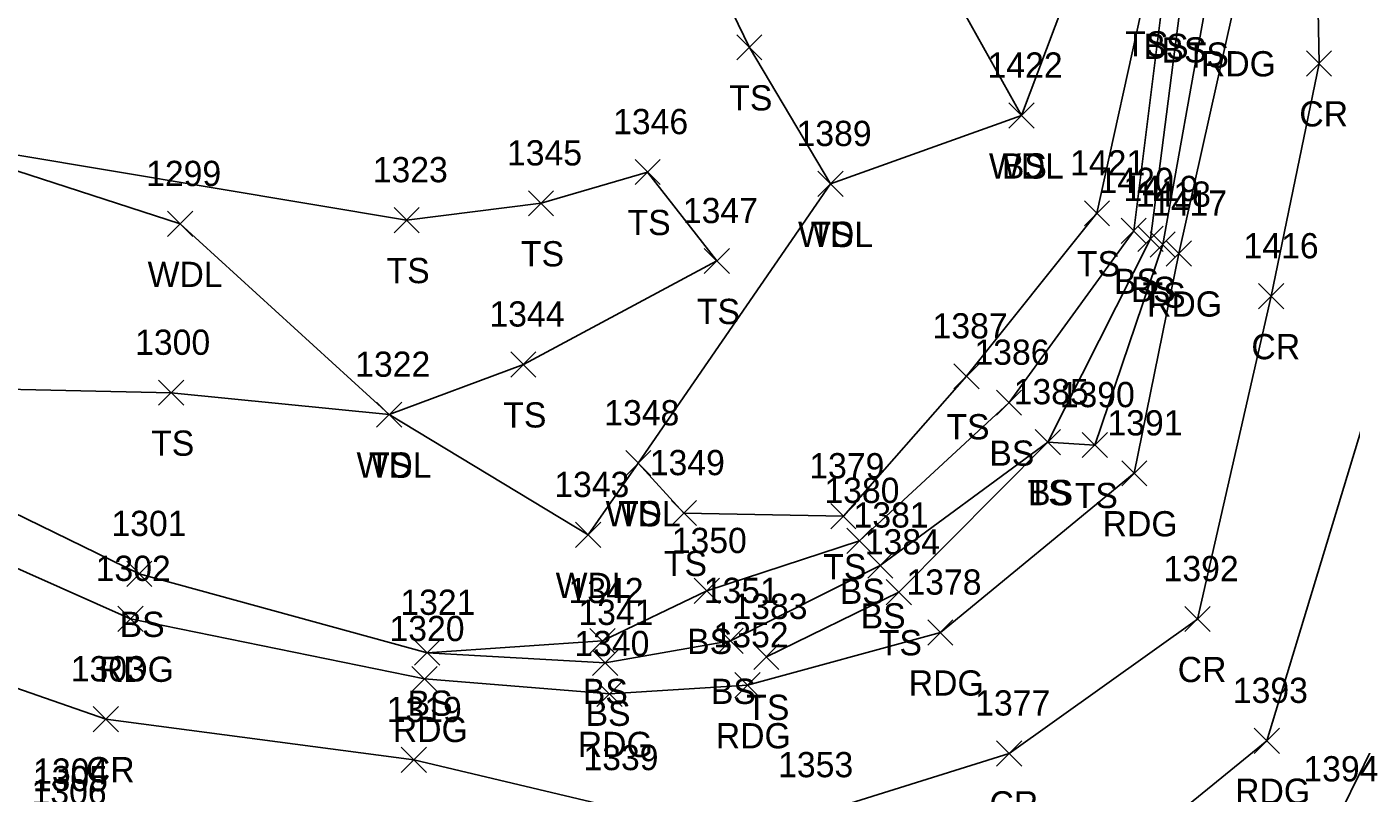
# Model space of a CAD drawing. Extents: x 1600281 to 1602254, y 862855 to 863227.
# Drawn here: x 1601927.2 to 1602032.3, y 862917.4 to 862978.2 of the extents above; entities that cross this region are included whole.
import ezdxf

# ---------------------------------------------------------------- set-up
doc = ezdxf.new("R2010")
doc.units = 0
for name, color, linetype in [('L_A', 7, 'Continuous'), ('L_I', 7, 'Continuous'), ('L_TIC', 7, 'Continuous'), ('LAWA', 7, 'Continuous'), ('LELB', 7, 'Continuous'), ('P_A', 7, 'Continuous'), ('P_I', 7, 'Continuous'), ('P_TIC', 7, 'Continuous'), ('PEU', 7, 'Continuous'), ('PRC', 7, 'Continuous')]:
    doc.layers.add(name, color=color, linetype=linetype)

msp = doc.modelspace()

# ---------------------------------------------------------------- linework, layer by layer
at = {"layer": 'L_TIC'}
for points in [[(1601983.53, 862975.52), (1601985.53, 862977.52)], [(1601985.53, 862975.52), (1601983.53, 862977.52)], [(1602005.1, 862970.12), (1602007.1, 862972.12)], [(1602007.1, 862970.12), (1602005.1, 862972.12)], [(1602005.1, 862970.12), (1602007.1, 862972.12)], [(1602007.1, 862970.12), (1602005.1, 862972.12)], [(1601975.47, 862965.64), (1601977.47, 862967.64)], [(1601977.47, 862965.64), (1601975.47, 862967.64)], [(1601989.97, 862964.7), (1601991.97, 862966.7)], [(1601991.97, 862964.7), (1601989.97, 862966.7)], [(1601989.97, 862964.7), (1601991.97, 862966.7)], [(1601991.97, 862964.7), (1601989.97, 862966.7)], [(1601967.02, 862963.16), (1601969.02, 862965.16)], [(1601969.02, 862963.16), (1601967.02, 862965.16)], [(1602011.08, 862962.37), (1602013.08, 862964.37)], [(1602013.08, 862962.37), (1602011.08, 862964.37)], [(1601938.42, 862961.53), (1601940.42, 862963.53)], [(1601940.42, 862961.53), (1601938.42, 862963.53)], [(1601956.37, 862961.83), (1601958.37, 862963.83)], [(1601958.37, 862961.83), (1601956.37, 862963.83)], [(1602013.99, 862960.98), (1602015.99, 862962.98)], [(1602015.99, 862960.98), (1602013.99, 862962.98)], [(1602015.32, 862960.34), (1602017.32, 862962.34)], [(1602017.32, 862960.34), (1602015.32, 862962.34)], [(1602016.29, 862959.89), (1602018.29, 862961.89)], [(1602018.29, 862959.89), (1602016.29, 862961.89)], [(1601980.96, 862958.59), (1601982.96, 862960.59)], [(1601982.96, 862958.59), (1601980.96, 862960.59)], [(1601980.96, 862958.59), (1601982.96, 862960.59)], [(1601982.96, 862958.59), (1601980.96, 862960.59)], [(1601965.62, 862950.39), (1601967.62, 862952.39)], [(1601967.62, 862950.39), (1601965.62, 862952.39)], [(1602000.74, 862949.45), (1602002.74, 862951.45)], [(1602002.74, 862949.45), (1602000.74, 862951.45)], [(1601937.71, 862948.15), (1601939.71, 862950.15)], [(1601939.71, 862948.15), (1601937.71, 862950.15)], [(1602004.11, 862947.36), (1602006.11, 862949.36)], [(1602006.11, 862947.36), (1602004.11, 862949.36)], [(1601954.99, 862946.41), (1601956.99, 862948.41)], [(1601956.99, 862946.41), (1601954.99, 862948.41)], [(1601954.99, 862946.41), (1601956.99, 862948.41)], [(1601956.99, 862946.41), (1601954.99, 862948.41)], [(1602007.18, 862944.23), (1602009.18, 862946.23)], [(1602009.18, 862944.23), (1602007.18, 862946.23)], [(1602007.18, 862944.23), (1602009.18, 862946.23)], [(1602009.18, 862944.23), (1602007.18, 862946.23)], [(1602010.91, 862944), (1602012.91, 862946)], [(1602012.91, 862944), (1602010.91, 862946)], [(1601974.73, 862942.56), (1601976.73, 862944.56)], [(1601976.73, 862942.56), (1601974.73, 862944.56)], [(1601974.73, 862942.56), (1601976.73, 862944.56)], [(1601976.73, 862942.56), (1601974.73, 862944.56)], [(1601978.35, 862938.61), (1601980.35, 862940.61)], [(1601980.35, 862938.61), (1601978.35, 862940.61)], [(1601990.98, 862938.36), (1601992.98, 862940.36)], [(1601992.98, 862938.36), (1601990.98, 862940.36)], [(1601990.98, 862938.36), (1601992.98, 862940.36)], [(1601992.98, 862938.36), (1601990.98, 862940.36)], [(1601970.76, 862936.88), (1601972.76, 862938.88)], [(1601972.76, 862936.88), (1601970.76, 862938.88)], [(1601992.26, 862936.41), (1601994.26, 862938.41)], [(1601994.26, 862936.41), (1601992.26, 862938.41)], [(1601935.18, 862933.79), (1601937.18, 862935.79)], [(1601937.18, 862933.79), (1601935.18, 862935.79)], [(1601993.91, 862934.46), (1601995.91, 862936.46)], [(1601995.91, 862934.46), (1601993.91, 862936.46)], [(1601980.16, 862932.44), (1601982.16, 862934.44)], [(1601982.16, 862932.44), (1601980.16, 862934.44)], [(1601995.38, 862932.33), (1601997.38, 862934.33)], [(1601997.38, 862932.33), (1601995.38, 862934.33)], [(1601971.89, 862928.47), (1601973.89, 862930.47)], [(1601973.89, 862928.47), (1601971.89, 862930.47)], [(1601982.04, 862928.48), (1601984.04, 862930.48)], [(1601984.04, 862928.48), (1601982.04, 862930.48)], [(1601958, 862927.54), (1601960, 862929.54)], [(1601960, 862927.54), (1601958, 862929.54)], [(1601958, 862927.54), (1601960, 862929.54)], [(1601960, 862927.54), (1601958, 862929.54)], [(1601972.11, 862926.74), (1601974.11, 862928.74)], [(1601974.11, 862926.74), (1601972.11, 862928.74)], [(1601984.88, 862927.21), (1601986.88, 862929.21)], [(1601986.88, 862927.21), (1601984.88, 862929.21)]]:
    msp.add_lwpolyline(points, dxfattribs=at)
at = {"layer": 'LAWA'}
for points in [[(1601918.48, 862969.32), (1601939.42, 862962.53), (1601955.99, 862947.41), (1601971.76, 862937.88), (1601975.73, 862943.56), (1601990.97, 862965.7), (1602006.1, 862971.12), (1602011.44, 862985.3), (1602010.41, 863001.06), (1602007, 863006.96), (1602005.73, 863016.36), (1602007.85, 863017.62), (1602015.33, 863025.06), (1602020.12, 863030.26)], [(1602013.88, 862864.6), (1602012.85, 862879.29), (1602012.39, 862885.25), (1602013.67, 862890.43), (1602013.99, 862891.89), (1602014.42, 862895.34), (1602031.13, 862915.34), (1602041.82, 862937), (1602041.48, 862949.37), (1602043.12, 862970.37), (1602043.1, 862998.4), (1602042.78, 863006.72), (1602043.56, 863021.7), (1602048.72, 863030.45), (1602052.92, 863023.58), (1602057.07, 863015.5), (1602062.85, 863014.97)]]:
    msp.add_lwpolyline(points, dxfattribs=at)
at = {"layer": 'LELB'}
for points in [[(1601850.49, 862982.97), (1601860.82, 862978.52), (1601879.36, 862968.78), (1601889.4, 862966.06), (1601913.79, 862945.71), (1601936.18, 862934.79), (1601959, 862928.54), (1601973.11, 862927.74), (1601983.04, 862929.48), (1601994.91, 862935.46), (1602008.18, 862945.23), (1602016.32, 862961.34), (1602018.76, 862980.32), (1602014.94, 863002.44), (1602007.85, 863017.62), (1602006.36, 863023.32), (1602003.16, 863037.99), (1602002.76, 863044.77), (1602006.6, 863051.13), (1602010.65, 863053.19)], [(1601959, 862928.54), (1601972.89, 862929.47), (1601981.16, 862933.44), (1601993.26, 862937.41), (1602005.11, 862948.36), (1602014.99, 862961.98), (1602017.33, 862980.6), (1602012.48, 863001.49), (1602005.73, 863016.36), (1601997.52, 863019.91), (1601988.34, 863030.35), (1601976.19, 863036.16)], [(1601985.88, 862928.21), (1601996.38, 862933.33), (1602008.18, 862945.23), (1602011.91, 862945), (1602017.29, 862960.89), (1602020.71, 862979.91), (1602019.4, 863003.13), (1602024.12, 863016.64), (1602028.23, 863030.49)], [(1602006.1, 862971.12), (1601997.07, 862987.32), (1601992.65, 862995.8), (1601988.46, 863008.93)], [(1601991.98, 862939.36), (1602001.74, 862950.45), (1602012.08, 862963.37), (1602015.91, 862980.8), (1602010.41, 863001.06)], [(1601907.64, 862983.21), (1601932.18, 862983.24), (1601948.6, 862984.2), (1601979.1, 862987.73), (1601984.53, 862976.52), (1601990.97, 862965.7)], [(1601762.59, 862962.68), (1601779.92, 862972.57), (1601804.03, 862980.87), (1601833.37, 862980.01), (1601850.49, 862982.97), (1601862.25, 862982.5), (1601869.46, 862981.7), (1601879.53, 862976.45), (1601887.39, 862976.99), (1601889.4, 862966.06), (1601914.82, 862949.68), (1601938.71, 862949.15), (1601955.99, 862947.41), (1601966.62, 862951.39), (1601981.96, 862959.59)], [(1601918.48, 862969.32), (1601957.37, 862962.83), (1601968.02, 862964.16), (1601976.47, 862966.64), (1601981.96, 862959.59)], [(1601975.73, 862943.56), (1601979.35, 862939.61), (1601991.98, 862939.36)]]:
    msp.add_lwpolyline(points, dxfattribs=at)
at = {"layer": 'P_TIC'}
for points in [[(1602028.68, 862974.25), (1602030.68, 862976.25)], [(1602030.68, 862974.25), (1602028.68, 862976.25)], [(1602017.56, 862959.18), (1602019.56, 862961.18)], [(1602019.56, 862959.18), (1602017.56, 862961.18)], [(1602024.88, 862955.8), (1602026.88, 862957.8)], [(1602026.88, 862955.8), (1602024.88, 862957.8)], [(1602014.04, 862941.76), (1602016.04, 862943.76)], [(1602016.04, 862941.76), (1602014.04, 862943.76)], [(1601934.49, 862930.23), (1601936.49, 862932.23)], [(1601936.49, 862930.23), (1601934.49, 862932.23)], [(1602019.05, 862930.21), (1602021.05, 862932.21)], [(1602021.05, 862930.21), (1602019.05, 862932.21)], [(1601998.67, 862929.14), (1602000.67, 862931.14)], [(1602000.67, 862929.14), (1601998.67, 862931.14)], [(1601957.79, 862925.46), (1601959.79, 862927.46)], [(1601959.79, 862925.46), (1601957.79, 862927.46)], [(1601972.44, 862924.27), (1601974.44, 862926.27)], [(1601974.44, 862924.27), (1601972.44, 862926.27)], [(1601983.38, 862924.96), (1601985.38, 862926.96)], [(1601985.38, 862924.96), (1601983.38, 862926.96)], [(1601932.52, 862922.27), (1601934.52, 862924.27)], [(1601934.52, 862922.27), (1601932.52, 862924.27)], [(1602024.54, 862920.56), (1602026.54, 862922.56)], [(1602026.54, 862920.56), (1602024.54, 862922.56)], [(1601956.93, 862919.04), (1601958.93, 862921.04)], [(1601958.93, 862919.04), (1601956.93, 862921.04)], [(1602004.13, 862919.56), (1602006.13, 862921.56)], [(1602006.13, 862919.56), (1602004.13, 862921.56)]]:
    msp.add_lwpolyline(points, dxfattribs=at)
at = {"layer": 'PEU'}
for points in [[(1601721.43, 862942.48), (1601759.39, 862940.42), (1601795.48, 862935.05), (1601824.44, 862931.28), (1601871.6, 862925.25), (1601900.95, 862923.39), (1601930.54, 862915.16), (1601956.45, 862910.48), (1601973.53, 862907.72), (1601992.87, 862904.84), (1602011.43, 862910.06), (1602025.54, 862921.56), (1602034.6, 862951.41), (1602037.17, 862973.14), (1602036.63, 863000.37), (1602039.38, 863008.7), (1602041.94, 863026.81), (1602046.4, 863038.48), (1602048.21, 863041.76), (1602041.55, 863045.82), (1602034.19, 863049.73), (1602032.2, 863046.61)], [(1601722.64, 862959.62), (1601760.79, 862956.05), (1601799.29, 862951.59), (1601828.84, 862949.76), (1601875.05, 862946.51), (1601907.83, 862943.55), (1601935.49, 862931.23), (1601958.79, 862926.46), (1601973.44, 862925.27), (1601984.38, 862925.96), (1601999.67, 862930.14), (1602015.04, 862942.76), (1602018.56, 862960.18), (1602022.83, 862979.22), (1602021.22, 863002.76), (1602025.96, 863016.12), (1602028.23, 863030.49), (1602032.2, 863046.61)]]:
    msp.add_lwpolyline(points, dxfattribs=at)
at = {"layer": 'PRC'}
msp.add_lwpolyline([(1601722.03, 862950.92), (1601760.35, 862947.65), (1601797.64, 862942.06), (1601826.1, 862939.87), (1601874.38, 862936.2), (1601906.56, 862932.66), (1601933.52, 862923.27), (1601957.93, 862920.04), (1601974.08, 862916.23), (1601989.5, 862915.67), (1602005.13, 862920.56), (1602020.05, 862931.21), (1602025.88, 862956.8), (1602029.68, 862975.25), (1602029.18, 863001.63), (1602032.15, 863012.73), (1602036.07, 863028.12), (1602041.55, 863045.82)], dxfattribs=at)

# ---------------------------------------------------------------- texts
at = {"layer": 'L_A'}
for s, p in [('TS', (1602014.32, 862975.8)), ('BS', (1602015.77, 862975.6)), ('BS', (1602017.2, 862975.32)), ('TS', (1602019.12, 862974.91)), ('TS', (1601982.94, 862971.52)), ('WDL', (1602003.52, 862966.12)), ('BS', (1602004.54, 862966.12)), ('TS', (1601974.88, 862961.64)), ('WDL', (1601988.39, 862960.7)), ('TS', (1601989.38, 862960.7)), ('TS', (1601966.43, 862959.16)), ('TS', (1601955.78, 862957.83)), ('TS', (1602010.49, 862958.37)), ('WDL', (1601936.84, 862957.53)), ('BS', (1602013.43, 862956.98)), ('BS', (1602014.76, 862956.34)), ('TS', (1602015.69, 862955.89)), ('TS', (1601980.37, 862954.59)), ('TS', (1601980.37, 862954.59)), ('TS', (1601965.03, 862946.39)), ('TS', (1602000.15, 862945.45)), ('TS', (1601937.12, 862944.15)), ('BS', (1602003.55, 862943.36)), ('WDL', (1601953.4, 862942.41)), ('TS', (1601954.39, 862942.41)), ('TS', (1602006.58, 862940.23)), ('BS', (1602006.62, 862940.23)), ('TS', (1602010.32, 862940)), ('WDL', (1601973.14, 862938.56)), ('TS', (1601974.13, 862938.56)), ('TS', (1601977.76, 862934.61)), ('TS', (1601990.39, 862934.36)), ('TS', (1601990.39, 862934.36)), ('WDL', (1601969.18, 862932.88)), ('BS', (1601991.7, 862932.41)), ('BS', (1601993.35, 862930.46)), ('BS', (1601934.62, 862929.79)), ('BS', (1601979.6, 862928.44)), ('TS', (1601994.79, 862928.33)), ('BS', (1601971.33, 862924.47)), ('BS', (1601981.48, 862924.48)), ('BS', (1601957.44, 862923.54)), ('BS', (1601957.44, 862923.54)), ('TS', (1601984.29, 862923.21)), ('BS', (1601971.55, 862922.74))]:
    msp.add_text(s, height=2, dxfattribs=at).set_placement(p)
at = {"layer": 'L_I'}
for s, p in [('1422', (1602003.41, 862974.12)), ('1422', (1602003.41, 862974.12)), ('1346', (1601973.73, 862969.64)), ('1389', (1601988.27, 862968.7)), ('1389', (1601988.27, 862968.7)), ('1345', (1601965.32, 862967.16)), ('1421', (1602009.95, 862966.37)), ('1299', (1601936.72, 862965.53)), ('1323', (1601954.68, 862965.83)), ('1420', (1602012.21, 862964.98)), ('1419', (1602014.18, 862964.34)), ('1418', (1602015.16, 862963.89)), ('1347', (1601979.26, 862962.59)), ('1347', (1601979.26, 862962.59)), ('1344', (1601963.93, 862954.39)), ('1387', (1601999.05, 862953.45)), ('1300', (1601935.85, 862952.15)), ('1322', (1601953.29, 862950.41)), ('1322', (1601953.29, 862950.41)), ('1386', (1602002.37, 862951.36)), ('1385', (1602005.48, 862948.23)), ('1385', (1602005.48, 862948.23)), ('1390', (1602009.13, 862948)), ('1348', (1601973.03, 862946.56)), ('1348', (1601973.03, 862946.56)), ('1349', (1601976.64, 862942.61)), ('1379', (1601989.28, 862942.36)), ('1379', (1601989.28, 862942.36)), ('1343', (1601969.07, 862940.88)), ('1380', (1601990.48, 862940.41)), ('1301', (1601933.97, 862937.79)), ('1381', (1601992.79, 862938.46)), ('1350', (1601978.38, 862936.44)), ('1384', (1601993.68, 862936.33)), ('1321', (1601956.87, 862931.54)), ('1321', (1601956.87, 862931.54)), ('1342', (1601970.2, 862932.47)), ('1351', (1601980.92, 862932.48)), ('1341', (1601970.98, 862930.74)), ('1383', (1601983.19, 862931.21)), ('1394', (1602028.44, 862918.34)), ('1305', (1601927.74, 862917.56)), ('1306', (1601927.64, 862916.51))]:
    msp.add_text(s, height=2, dxfattribs=at).set_placement(p)
at = {"layer": 'P_A'}
for s, p in [('RDG', (1602020.32, 862974.22)), ('CR', (1602028.12, 862970.25)), ('RDG', (1602016.05, 862955.18)), ('CR', (1602024.32, 862951.8)), ('RDG', (1602012.53, 862937.76)), ('RDG', (1601932.98, 862926.23)), ('CR', (1602018.48, 862926.21)), ('RDG', (1601997.16, 862925.14)), ('RDG', (1601956.27, 862921.46)), ('RDG', (1601970.93, 862920.27)), ('RDG', (1601981.87, 862920.96)), ('CR', (1601931.95, 862918.27)), ('RDG', (1602023.03, 862916.56)), ('CR', (1602003.56, 862915.56))]:
    msp.add_text(s, height=2, dxfattribs=at).set_placement(p)
at = {"layer": 'P_I'}
for s, p in [('1417', (1602016.44, 862963.18)), ('1416', (1602023.7, 862959.8)), ('1391', (1602012.91, 862945.76)), ('1302', (1601932.72, 862934.23)), ('1392', (1602017.36, 862934.21)), ('1378', (1601996.98, 862933.14)), ('1320', (1601956.01, 862929.46)), ('1352', (1601981.69, 862928.96)), ('1340', (1601970.66, 862928.27)), ('1303', (1601930.75, 862926.27)), ('1393', (1602022.85, 862924.56)), ('1377', (1602002.43, 862923.56)), ('1319', (1601955.79, 862923.04)), ('1339', (1601971.38, 862919.23)), ('1304', (1601927.77, 862918.16)), ('1353', (1601986.81, 862918.67))]:
    msp.add_text(s, height=2, dxfattribs=at).set_placement(p)

doc.saveas('drawing.dxf')
